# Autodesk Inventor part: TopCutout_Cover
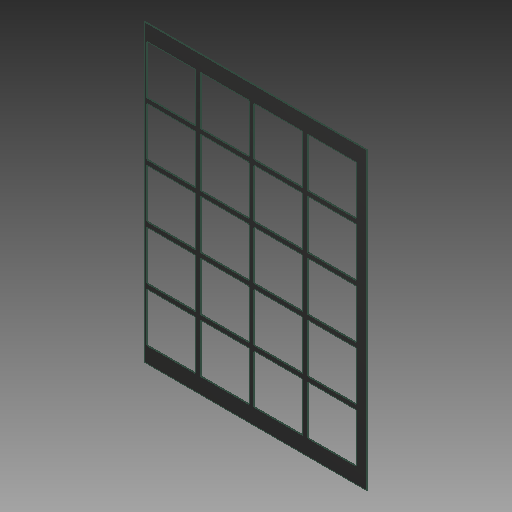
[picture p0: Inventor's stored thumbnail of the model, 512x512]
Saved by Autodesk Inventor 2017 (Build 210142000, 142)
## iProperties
Created: 2017-05
Part Number: TopCutout_Cover
Material: Generic
Document SubType Name: Modeling
Designer: Savy
Density: 1 g/cm^3
Appearance: Default
Author: Savy
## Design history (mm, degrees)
feature "SOLID1"
body "Solid1"
